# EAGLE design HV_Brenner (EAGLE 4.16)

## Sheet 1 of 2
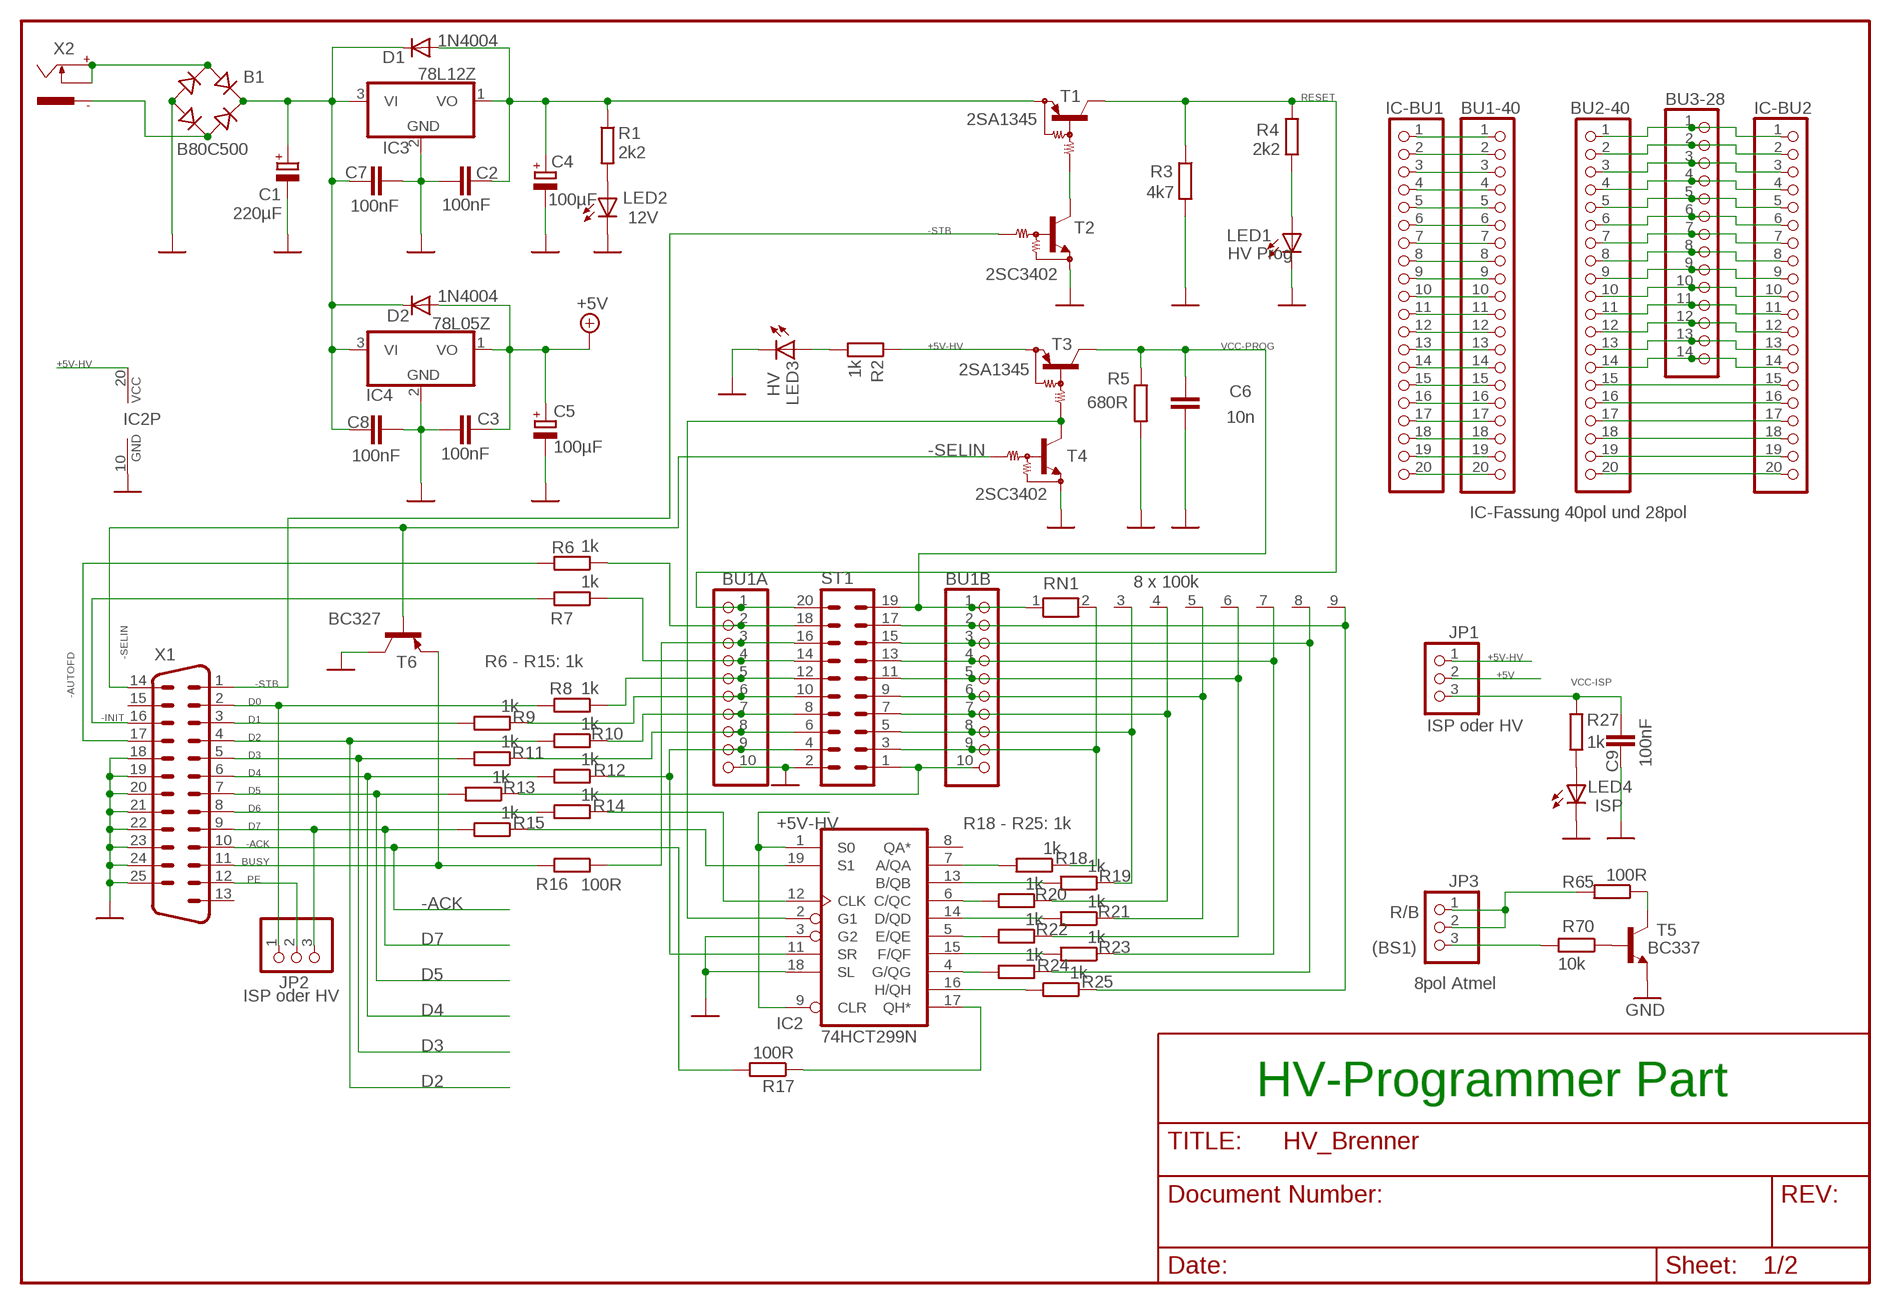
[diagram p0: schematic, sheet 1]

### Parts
B1  B80C500  B-DIL  [B-DIL]
BU1-40  PINHD-1X20  [1X20]
BU1A  PINHD-1X10  [1X10]
BU1B  PINHD-1X10  [1X10]
BU2-40  PINHD-1X20  [1X20]
BU3-28  PINHD-1X14  [1X14]
C1  220µF  CPOL-EUE3.5-8  [E3,5-8]
C2  100nF  C-EU025-024X044  [C025-024X044]
C3  100nF  C-EU025-024X044  [C025-024X044]
C4  100µF  CPOL-EUE2.5-7  [E2,5-7]
C5  100µF  CPOL-EUE2.5-7  [E2,5-7]
C6  10n  C-EU025-024X044  [C025-024X044]
C7  100nF  C-EU025-024X044  [C025-024X044]
C8  100nF  C-EU025-024X044  [C025-024X044]
C9  100nF  C-EU025-024X044  [C025-024X044]
D1  1N4004  [DO41-10]
D2  1N4004  [DO41-10]
IC2  74HCT299N  74ACT299N  [DIL20]
IC3  78L12Z  [TO92]
IC4  78L05Z  [TO92]
IC-BU1  PINHD-1X20  [1X20]
IC-BU2  PINHD-1X20  [1X20]
JP1  ISP oder HV  PINHD-1X3  [1X03]
JP2  ISP oder HV  PINHD-1X3  [1X03]
JP3  8pol Atmel  PINHD-1X3  [1X03]
LED1  HV Prog  LED3MM  [LED3MM]
LED2  12V  LED3MM  [LED3MM]
LED3  HV  LED3MM  [LED3MM]
LED4  ISP  LED3MM  [LED3MM]
R1  2k2  R-EU_0204/2V  [0204V]
R2  1k  R-EU_0204/2V  [0204V]
R3  4k7  R-EU_0204/2V  [0204V]
R4  2k2  R-EU_0204/2V  [0204V]
R5  680R  R-EU_0204/2V  [0204V]
R6  1k  R-EU_0204/2V  [0204V]
R7  1k  R-EU_0204/2V  [0204V]
R8  1k  R-EU_0204/2V  [0204V]
R9  1k  R-EU_0204/2V  [0204V]
R10  1k  R-EU_0204/2V  [0204V]
R11  1k  R-EU_0204/2V  [0204V]
R12  1k  R-EU_0204/2V  [0204V]
R13  1k  R-EU_0204/2V  [0204V]
R14  1k  R-EU_0204/2V  [0204V]
R15  1k  R-EU_0204/2V  [0204V]
R16  100R  R-EU_0204/2V  [0204V]
R17  100R  R-EU_0204/2V  [0204V]
R18  1k  R-EU_0204/2V  [0204V]
R19  1k  R-EU_0204/2V  [0204V]
R20  1k  R-EU_0204/2V  [0204V]
R21  1k  R-EU_0204/2V  [0204V]
R22  1k  R-EU_0204/2V  [0204V]
R23  1k  R-EU_0204/2V  [0204V]
R24  1k  R-EU_0204/2V  [0204V]
R25  1k  R-EU_0204/2V  [0204V]
R27  1k  R-EU_0204/2V  [0204V]
R65  100R  R-EU_0204/2V  [0204V]
R70  10k  R-EU_0204/2V  [0204V]
RN1  8 x 100k  RN08  [RN-9]
ST1  ML20  [ML20]
T1  2SA1345  2SC1345  [TO92-BCE]
T2  2SC3402  2SA3402  [TO92-BCE]
T3  2SA1345  2SC1345  [TO92-BCE]
T4  2SC3402  2SA3402  [TO92-BCE]
T5  BC337  [TO92]
T6  BC327  [TO92]
X1  M25HP  [M25HP]
X2  737992-55  [737992-5]

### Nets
#BS1: JP3.3 R70.2
#R/B: JP3.1 JP3.2 R65.2
+5V: C3.2 C5.+ D2.A IC4.1(VO) JP1.2
+5V-HV: IC2.1(S0) IC2.9(CLR) IC2.20(VCC) JP1.1 R2.1 T3.E
+12V: C2.2 C4.+ D1.A IC3.1(VO) R1.1 T1.E
+VIN: B1.+ C1.+ C7.1 C8.1 D1.C D2.C IC3.3(VI) IC4.3(VI)
-ACK: R17.2 X1.10 ; also sheet 2
-AUTOFD: R6.2 X1.17
-INIT: R7.2 X1.16
-SELIN: T4.B T6.2(B) X1.14
-STB: T2.B X1.1
AC1: B1.AC1 X2.+ X2.K
AC2: B1.AC2 X2.-1
BS1: BU1A.8 R11.1 ST1.6
BS2: BU1A.4 R7.1 ST1.14
BUSY: R16.2 T6.1(E) X1.11 ; also sheet 2
D0: JP2.1 R8.2 X1.2
D1: R9.2 X1.3 ; also sheet 2
D2: R10.2 X1.4 ; also sheet 2
D3: R11.2 X1.5 ; also sheet 2
D4: R12.2 X1.6 ; also sheet 2
D5: R13.2 X1.7 ; also sheet 2
D6: R14.2 X1.8
D7: JP2.3 R15.2 X1.9 ; also sheet 2
DATA0: BU1B.9 R18.1 RN1.2 ST1.3
DATA1: BU1B.8 R19.1 RN1.3 ST1.5
DATA2: BU1B.7 R20.1 RN1.4 ST1.7
DATA3: BU1B.6 R21.1 RN1.5 ST1.9
DATA4: BU1B.5 R22.1 RN1.6 ST1.11
DATA5: BU1B.4 R23.1 RN1.7 ST1.13
DATA6: BU1B.3 R24.1 RN1.8 ST1.15
DATA7: BU1B.2 R25.1 RN1.9 ST1.17
GND: B1.- BU1A.10 C1.- C2.1 C3.1 C4.- C5.- C6.2 C7.2 C8.2 C9.1 IC2.3(G2) IC2.10(GND) IC2.18(SL) IC3.2(GND) IC4.2(GND) LED1.K(C) LED2.K(C) LED3.K(C) LED4.K(C) R3.2 R5.2 ST1.2 T2.E T4.E T5.1(E) T6.3(C) X1.18 X1.19 X1.20 X1.21 X1.22 X1.23 X1.24 X1.25 ; also sheet 2
N$1: R65.1 T5.3(C)
N$2: LED1.A R4.2
N$4: R70.1 T5.2(B)
N$5: T1.B T2.C
N$6: IC2.2(G1) T3.B T4.C
N$34: BU2-40.1 BU3-28.1 IC-BU2.1
N$35: BU2-40.2 BU3-28.2 IC-BU2.2
N$36: BU2-40.3 BU3-28.3 IC-BU2.3
N$37: BU2-40.4 BU3-28.4 IC-BU2.4
N$38: BU2-40.5 BU3-28.5 IC-BU2.5
N$39: BU2-40.6 BU3-28.6 IC-BU2.6
N$40: BU2-40.7 BU3-28.7 IC-BU2.7
N$41: BU2-40.8 BU3-28.8 IC-BU2.8
N$42: BU2-40.9 BU3-28.9 IC-BU2.9
N$43: BU2-40.10 BU3-28.10 IC-BU2.10
N$44: BU2-40.11 BU3-28.11 IC-BU2.11
N$45: BU2-40.12 BU3-28.12 IC-BU2.12
N$46: BU2-40.13 BU3-28.13 IC-BU2.13
N$47: BU2-40.14 BU3-28.14 IC-BU2.14
N$48: BU2-40.15 IC-BU2.15
N$49: BU2-40.16 IC-BU2.16
N$50: BU2-40.17 IC-BU2.17
N$51: BU2-40.18 IC-BU2.18
N$52: BU2-40.19 IC-BU2.19
N$53: BU2-40.20 IC-BU2.20
N$54: BU1-40.1 IC-BU1.1
N$55: BU1-40.2 IC-BU1.2
N$56: BU1-40.3 IC-BU1.3
N$57: BU1-40.4 IC-BU1.4
N$58: BU1-40.5 IC-BU1.5
N$59: BU1-40.6 IC-BU1.6
N$60: BU1-40.7 IC-BU1.7
N$61: BU1-40.8 IC-BU1.8
N$62: BU1-40.9 IC-BU1.9
N$63: BU1-40.10 IC-BU1.10
N$64: BU1-40.11 IC-BU1.11
N$65: BU1-40.12 IC-BU1.12
N$66: BU1-40.13 IC-BU1.13
N$67: BU1-40.14 IC-BU1.14
N$68: BU1-40.15 IC-BU1.15
N$69: BU1-40.16 IC-BU1.16
N$70: BU1-40.17 IC-BU1.17
N$71: BU1-40.18 IC-BU1.18
N$72: BU1-40.19 IC-BU1.19
N$73: BU1-40.20 IC-BU1.20
N$74: LED2.A R1.2
N$75: IC2.17(QH*) R17.1
N$76: LED3.A R2.2
N$77: IC2.7(A/QA) R18.2
N$78: IC2.13(B/QB) R19.2
N$79: IC2.19(S1) R15.1
N$80: IC2.12(CLK) R14.1
N$81: IC2.6(C/QC) R20.2
N$82: IC2.14(D/QD) R21.2
N$83: IC2.5(E/QE) R22.2
N$84: IC2.15(F/QF) R23.2
N$85: IC2.4(G/QG) R24.2
N$86: IC2.16(H/QH) R25.2
N$166: LED4.A R27.2
OE: BU1A.6 R9.1 ST1.10
PAGEL: BU1A.2 R6.1 ST1.18
PE: JP2.2 X1.12
R/B: BU1A.3 R16.1 ST1.16
RESET: BU1A.1 R3.1 R4.1 ST1.20 T1.C
VCC-ISP: C9.2 JP1.3 R27.1 ; also sheet 2
VCC-PROG: BU1B.1 C6.1 R5.1 RN1.1 ST1.19 T3.C
WR: BU1A.7 R10.1 ST1.8
XA0: BU1A.9 IC2.11(SR) R12.1 ST1.4
XA1: BU1B.10 R13.1 ST1.1
XTAL1: BU1A.5 R8.1 ST1.12
Unconnected: IC2.8(QA*) X1.13 X1.15 X2.-2

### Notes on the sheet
- IC-Fassung 40pol und 28pol
- R6 - R15: 1k
- R18 - R25: 1k
- R/B
- (BS1)
- HV-Programmer Part

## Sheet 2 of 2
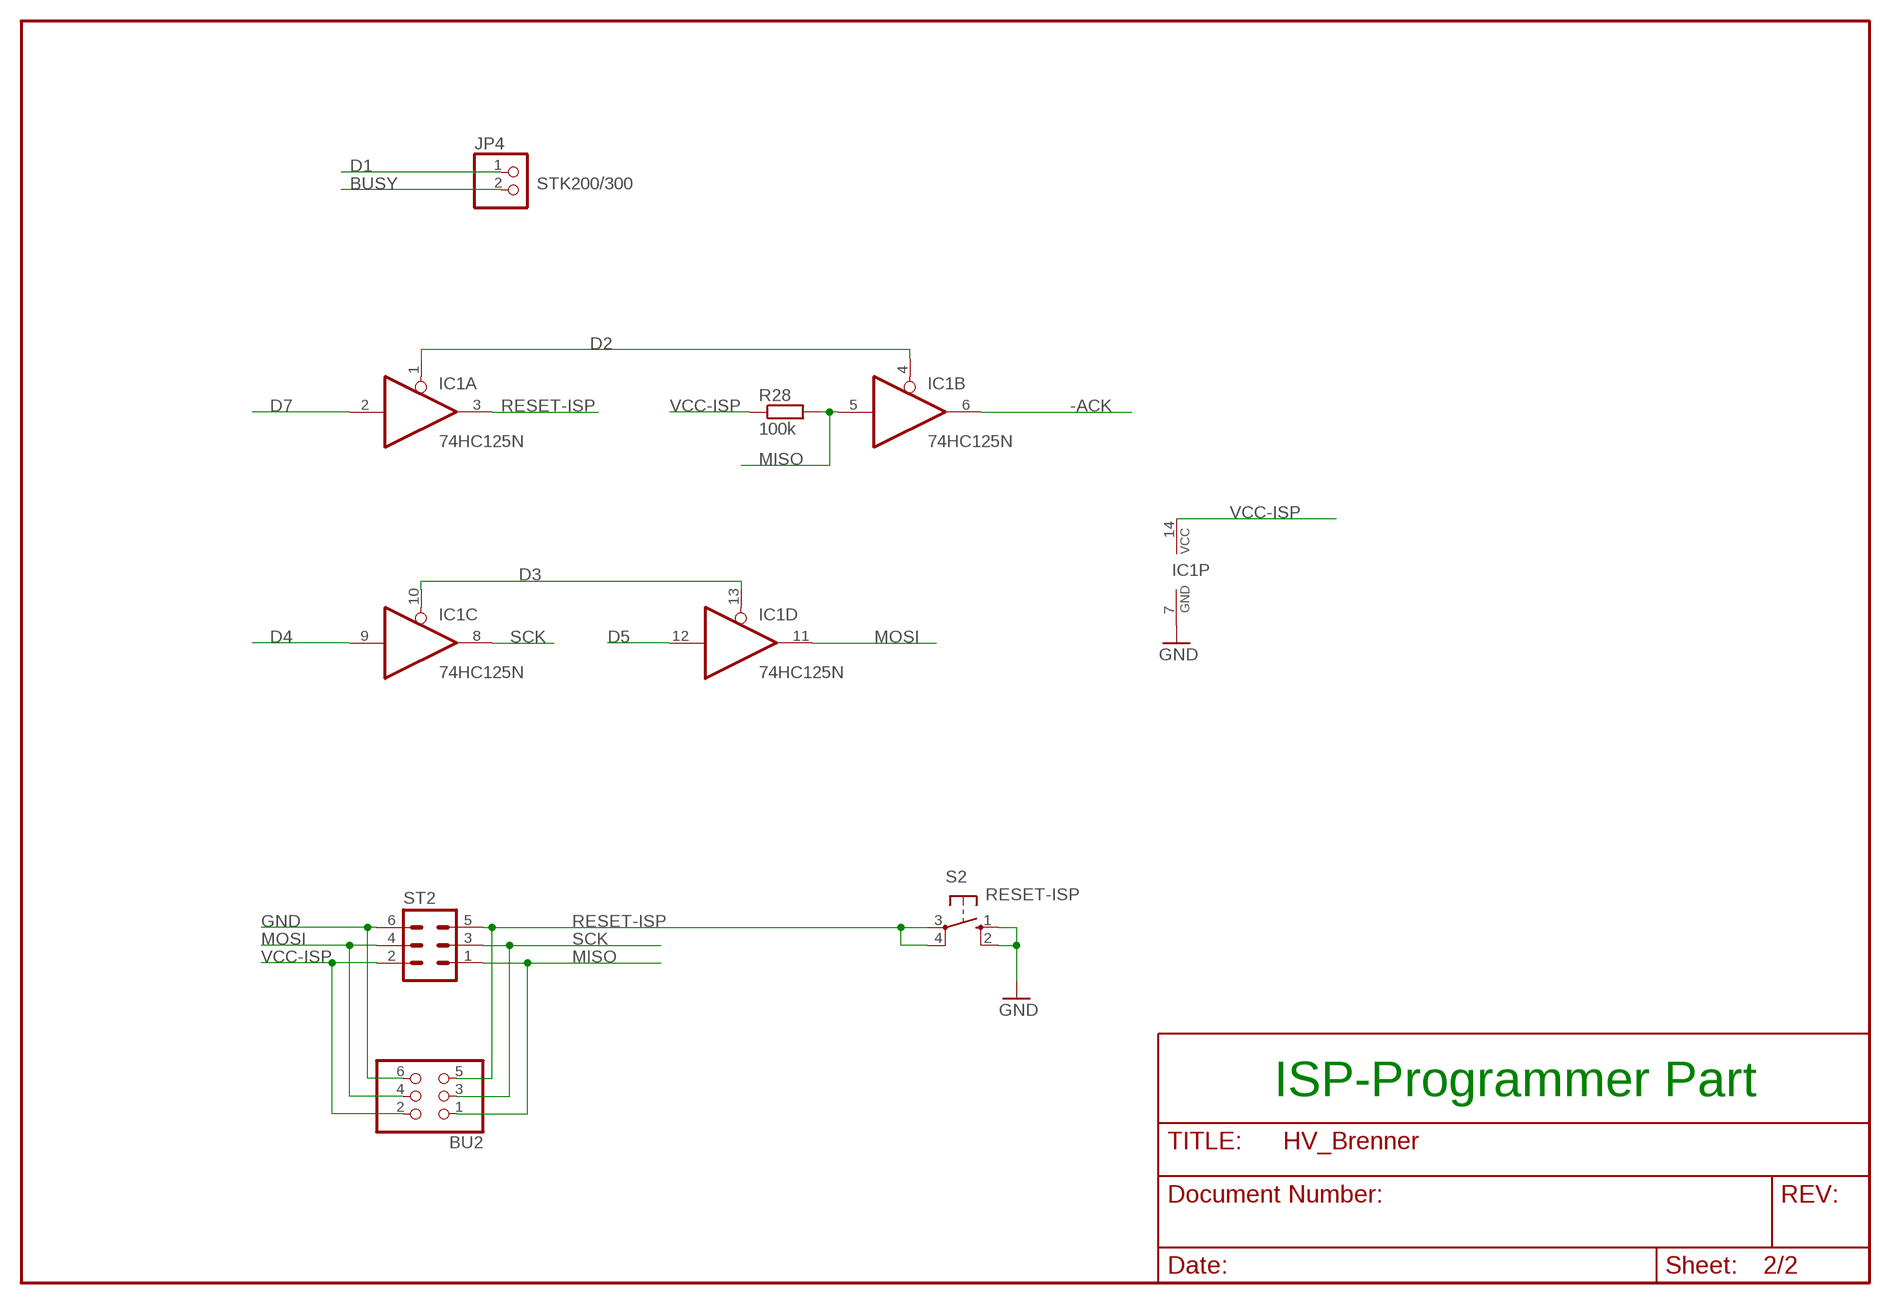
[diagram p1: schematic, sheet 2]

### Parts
BU2  PINHD-2X3  [2X03]
IC1  74HC125N  [DIL14]
JP4  PINHD-1X2  [1X02]
R28  100k  R-EU_0204/2V  [0204V]
S2  RESET-ISP  10-XX  [B3F-10XX]
ST2  ML6  [ML6]

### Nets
-ACK: IC1.6(B:O) ; also sheet 1
BUSY: JP4.2 ; also sheet 1
D1: JP4.1 ; also sheet 1
D2: IC1.1(A:OE) IC1.4(B:OE) ; also sheet 1
D3: IC1.10(C:OE) IC1.13(D:OE) ; also sheet 1
D4: IC1.9(C:I) ; also sheet 1
D5: IC1.12(D:I) ; also sheet 1
D7: IC1.2(A:I) ; also sheet 1
GND: BU2.6 IC1.7(P:GND) S2.1(S) S2.2(S1) ST2.6 ; also sheet 1
MISO: BU2.1 IC1.5(B:I) R28.2 ST2.1
MOSI: BU2.4 IC1.11(D:O) ST2.4
RESET-ISP: BU2.5 IC1.3(A:O) S2.3(P) S2.4(P1) ST2.5
SCK: BU2.3 IC1.8(C:O) ST2.3
VCC-ISP: BU2.2 IC1.14(P:VCC) R28.1 ST2.2 ; also sheet 1

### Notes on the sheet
- STK200/300
- ISP-Programmer Part

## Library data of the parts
B1 = rectifier:B-DIL: RECTIFIER
BU1-40 BU2-40 IC-BU1 IC-BU2 = pinhead:PINHD-1X20: PIN HEADER
BU1A BU1B = pinhead:PINHD-1X10: PIN HEADER
BU2 = pinhead:PINHD-2X3: PIN HEADER
BU3-28 = pinhead:PINHD-1X14: PIN HEADER
C1 C4 C5 = rcl:CPOL-EU: POLARIZED CAPACITOR, European symbol
C2 C3 C6-C9 = rcl:C-EU: CAPACITOR, European symbol
D1 D2 = diode:1N4004: DIODE
IC1 = 74xx-eu:74*125: Quad bus BUFFER, 3-state
IC2 = 74xx-eu:74*299: 8-bit universal SHIFT/STORAGE REGISTER
IC3 IC4 = linear:78*: Positive VOLTAGE REGULATOR Source: http://cache.national.com/ds/LM/LM78L05.pdf http://www.fairchildsemi.com/ds/LM/LM7805.pdf
JP1-JP3 = pinhead:PINHD-1X3: PIN HEADER
JP4 = pinhead:PINHD-1X2: PIN HEADER
LED1-LED4 = led:LED: LED
R1-R25 R27 R28 R65 R70 = rcl:R-EU_: RESISTOR, European symbol
RN1 = resistor-net:RN08: RESISTOR NETWORK
S2 = switch-omron:10-XX: OMRON SWITCH
ST1 = con-harting-ml:ML20: HARTING
ST2 = con-harting-ml:ML6: HARTING
T1 T3 = transistor:2SC1345
T2 T4 = transistor:2SA3402
T5 = transistor:BC337: NPN TRANSISTOR
T6 = transistor-pnp:BC327: PNP Transistor
X1 = con-subd:M25: SUB-D
X2 = con-conrad:737992-55: FEMALE PRINT CONNECTOR DIN 45323 (34V/3A), ROKA, distributor Conrad

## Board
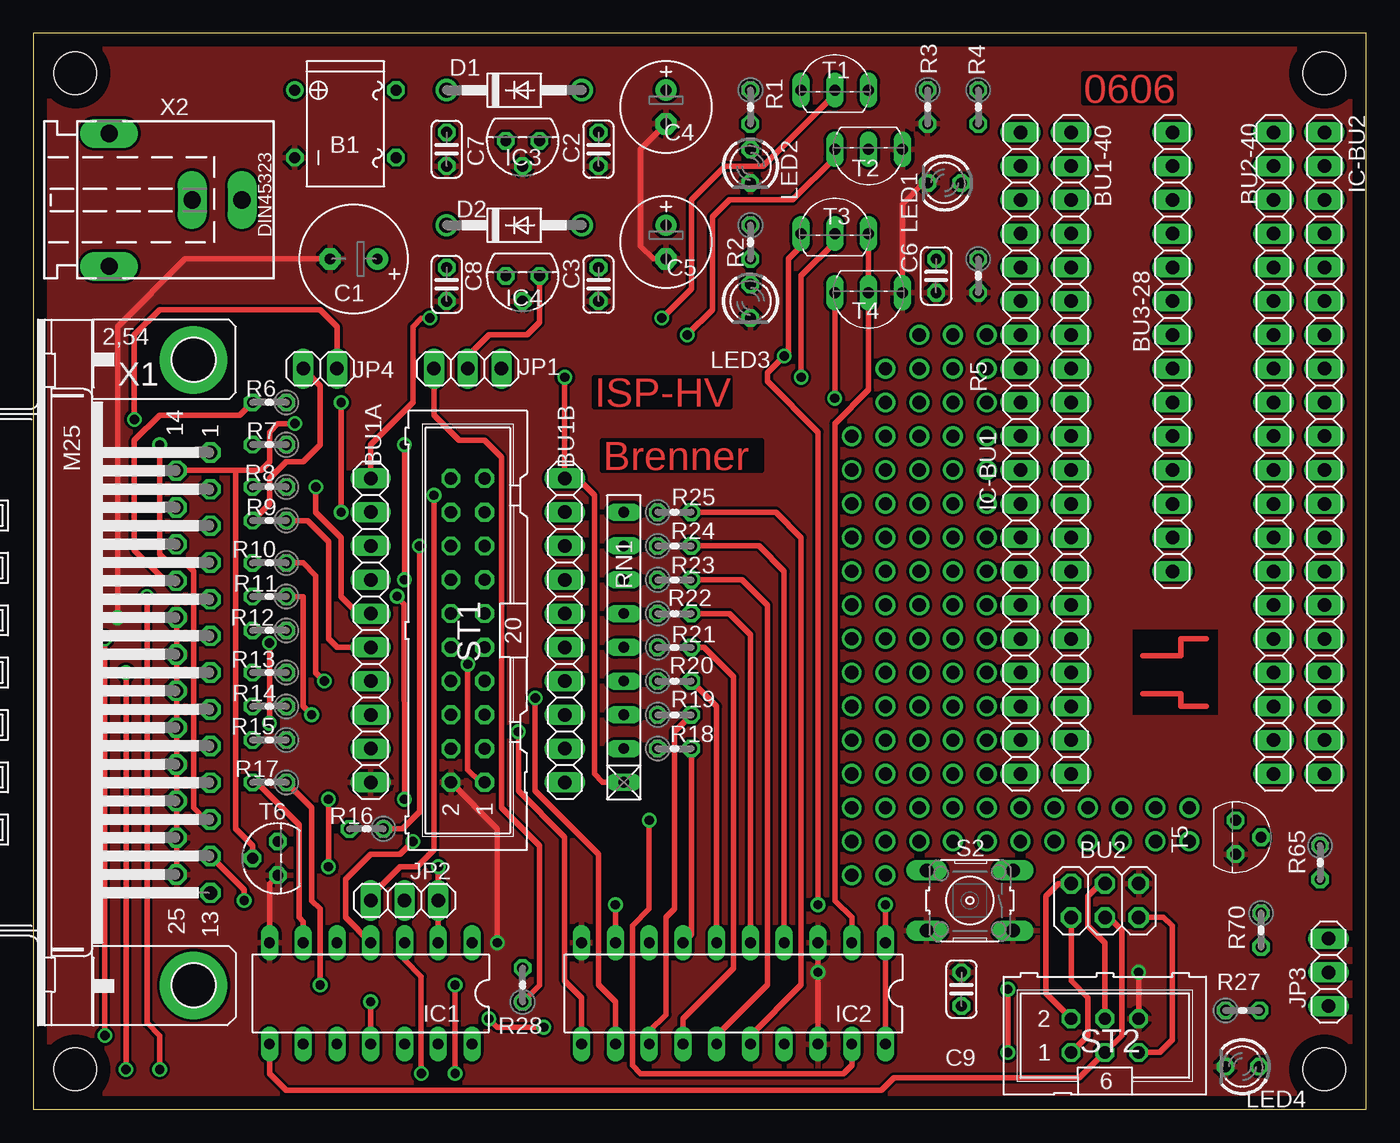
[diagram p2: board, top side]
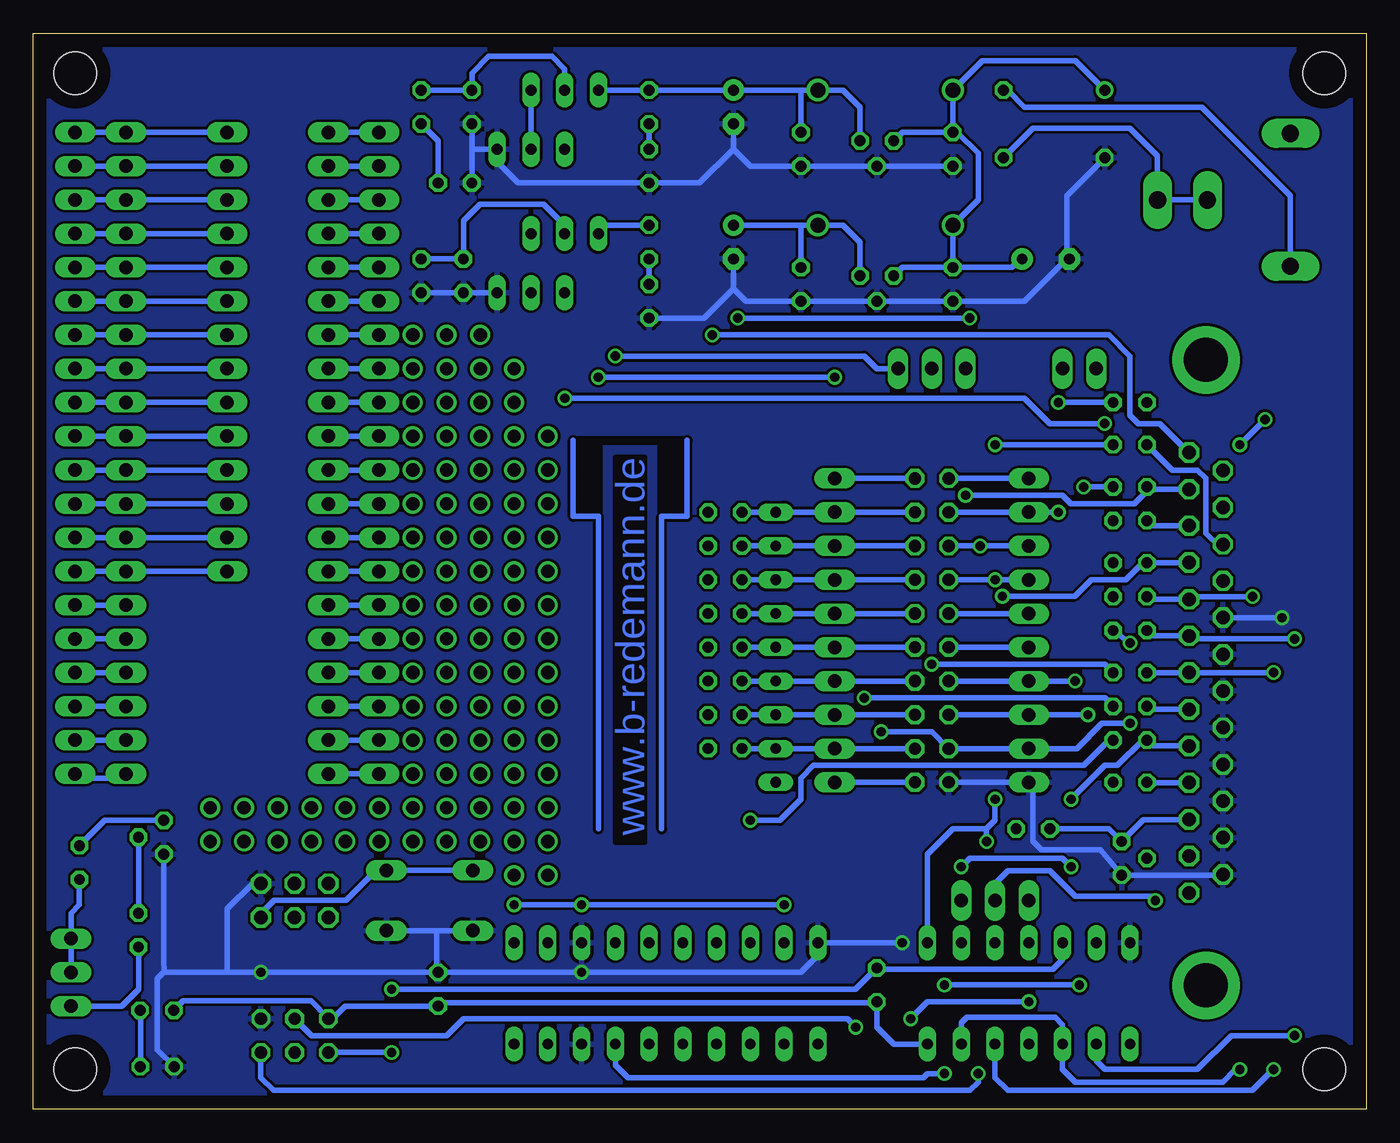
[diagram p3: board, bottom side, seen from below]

Size 100.31 x 80.95 mm. Coordinates in mm from the lower left corner, seen from the top.
Outline: 0,0 100.31,0 100.31,80.95 0,80.95 0,0
Copper layers (1+16): Top 0.035mm / dielectric 1.5mm / Bottom 0.035mm
Design rules "default": minimum track width 10mil, minimum drill 24mil, track to track 8mil, track to pad 8mil, pad to pad 8mil, via to via 8mil, smd to smd 8mil, copper to edge 40mil, drill to drill 8mil, minimum pad ring 10mil, minimum via ring 8mil, stop-mask expansion 4mil, vias tented up to drill 0mil, thermal gap 10mil
Holes 3.2 mm at 3.17,77.94 3.17,3.01 97.15,3.01 97.15,77.94
tRestrict: area 82.7,35.7 to 89.1,36.1; area 82.7,29.7 to 89.1,30.1; area 82.7,30.1 to 83.1,35.7; area 88.7,30.1 to 89.1,35.7
bRestrict: area 57.5,44.9 to 59.4,50.6; area 53.7,50 to 57.5,50.6; area 51.4,44.9 to 53.3,50.6; area 53.3,50 to 53.7,50.6

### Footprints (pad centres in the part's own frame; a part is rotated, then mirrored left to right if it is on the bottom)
B-DIL = drill 0.813 round: + -2.54,-3.81 | drill 0.813 octagon: - 2.54,-3.81; AC1 2.54,3.81; AC2 -2.54,3.81
1X20 = drill 1.016 long: 1 -24.13,0; 2 -21.59,0; 3 -19.05,0; 4 -16.51,0; 5 -13.97,0; 6 -11.43,0; 7 -8.89,0; 8 -6.35,0; 9 -3.81,0; 10 -1.27,0; 11 1.27,0; 12 3.81,0; 13 6.35,0; 14 8.89,0; 15 11.43,0; 16 13.97,0; 17 16.51,0; 18 19.05,0; 19 21.59,0; 20 24.13,0
1X10 = drill 1.016 long: 1 -11.43,0; 2 -8.89,0; 3 -6.35,0; 4 -3.81,0; 5 -1.27,0; 6 1.27,0; 7 3.81,0; 8 6.35,0; 9 8.89,0; 10 11.43,0
2X03 = drill 1.016 octagon: 1 -2.54,-1.27; 2 -2.54,1.27; 3 0,-1.27; 4 0,1.27; 5 2.54,-1.27; 6 2.54,1.27
1X14 = drill 1.016 long: 1 -16.51,0; 2 -13.97,0; 3 -11.43,0; 4 -8.89,0; 5 -6.35,0; 6 -3.81,0; 7 -1.27,0; 8 1.27,0; 9 3.81,0; 10 6.35,0; 11 8.89,0; 12 11.43,0; 13 13.97,0; 14 16.51,0
E3,5-8 = drill 0.813 pad 1.6 round: + -1.778,0 | drill 0.813 pad 1.6 octagon: - 1.778,0
C025-024X044 = drill 0.813 octagon: 1 -1.27,0; 2 1.27,0
E2,5-7 = drill 0.813 pad 1.6 round: + -1.27,0 | drill 0.813 pad 1.6 octagon: - 1.27,0
DO41-10 = drill 1.118 round: A 5.08,0; C -5.08,0
DIL14 = drill 0.813 long: 1 -7.62,-3.81; 2 -5.08,-3.81; 3 -2.54,-3.81; 4 0,-3.81; 5 2.54,-3.81; 6 5.08,-3.81; 7 7.62,-3.81; 8 7.62,3.81; 9 5.08,3.81; 10 2.54,3.81; 11 0,3.81; 12 -2.54,3.81; 13 -5.08,3.81; 14 -7.62,3.81
DIL20 = drill 0.813 long: 1 -11.43,-3.81; 2 -8.89,-3.81; 3 -6.35,-3.81; 4 -3.81,-3.81; 5 -1.27,-3.81; 6 1.27,-3.81; 7 3.81,-3.81; 8 6.35,-3.81; 9 8.89,-3.81; 10 11.43,-3.81; 11 11.43,3.81; 12 8.89,3.81; 13 6.35,3.81; 14 3.81,3.81; 15 1.27,3.81; 16 -1.27,3.81; 17 -3.81,3.81; 18 -6.35,3.81; 19 -8.89,3.81; 20 -11.43,3.81
TO92 = drill 0.813 octagon: 1 -1.27,0; 2 0,1.905; 3 1.27,0
1X03 = drill 1.016 long: 1 -2.54,0; 2 0,0; 3 2.54,0
1X02 = drill 1.016 long: 1 -1.27,0; 2 1.27,0
LED3MM = drill 0.813 octagon: A -1.27,0; K 1.27,0
0204V = drill 0.813 octagon: 1 -1.27,0; 2 1.27,0
RN-9 = drill 0.813 long: 1 -10.16,0; 2 -7.62,0; 3 -5.08,0; 4 -2.54,0; 5 0,0; 6 2.54,0; 7 5.08,0; 8 7.62,0; 9 10.16,0
B3F-10XX = drill 1.016 long: 1 -3.251,2.261; 2 3.251,2.261; 3 -3.251,-2.261; 4 3.251,-2.261
ML20 = drill 0.914 octagon: 1 -11.43,-1.27; 2 -11.43,1.27; 3 -8.89,-1.27; 4 -8.89,1.27; 5 -6.35,-1.27; 6 -6.35,1.27; 7 -3.81,-1.27; 8 -3.81,1.27; 9 -1.27,-1.27; 10 -1.27,1.27; 11 1.27,-1.27; 12 1.27,1.27; 13 3.81,-1.27; 14 3.81,1.27; 15 6.35,-1.27; 16 6.35,1.27; 17 8.89,-1.27; 18 8.89,1.27; 19 11.43,-1.27; 20 11.43,1.27
ML6 = drill 0.914 octagon: 1 -2.54,-1.27; 2 -2.54,1.27; 3 0,-1.27; 4 0,1.27; 5 2.54,-1.27; 6 2.54,1.27
TO92-BCE = drill 0.813 long: B 2.54,0; C 0,0; E -2.54,0
TO92' = drill 0.813 octagon: 1 1.27,0; 2 0,1.905; 3 -1.27,0
M25HP = drill 1.016 octagon: 1 -16.561,1.27; 2 -13.792,1.27; 3 -11.049,1.27; 4 -8.28,1.27; 5 -5.512,1.27; 6 -2.769,1.27; 7 0,1.27; 8 2.769,1.27; 9 5.512,1.27; 10 8.28,1.27; 11 11.049,1.27; 12 13.792,1.27; 13 16.561,1.27; 14 -15.189,-1.27; 15 -12.421,-1.27; 16 -9.652,-1.27; 17 -6.909,-1.27; 18 -4.14,-1.27; 19 -1.372,-1.27; 20 1.372,-1.27; 21 4.14,-1.27; 22 6.909,-1.27; 23 9.652,-1.27; 24 12.421,-1.27; 25 15.189,-1.27 | drill 3.302 pad 5.08 round: G1 -23.52,0; G2 23.52,0
737992-5 = drill 1.3 pad 2.184 long: + 0,10; -1 5,0; -2 -5,0; K 0,6.25

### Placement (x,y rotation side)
B1  23.49,74.13 270 top
BU1-40  78.1,49.37 270 top
BU1A  25.39,36.03 270 top
BU1B  40,36.03 270 top
BU2  80.64,15.71 0 top
BU2-40  93.34,49.37 270 top
BU3-28  85.72,56.98 270 top
C1  24.12,63.97 180 top
C2  42.54,72.22 90 top
C3  42.54,62.06 90 top
C4  47.62,75.4 270 top
C5  47.62,65.24 270 top
C6  67.94,62.7 270 top
C7  31.11,72.22 270 top
C8  31.11,62.06 270 top
C9  69.84,9.04 270 top
D1  36.19,76.67 0 top
D2  36.19,66.51 0 top
IC1  25.39,8.73 180 top
IC2  52.7,8.73 180 top
IC3  36.83,72.86 180 top
IC4  36.83,62.7 180 top
IC-BU1  74.29,49.37 270 top
IC-BU2  97.15,49.37 270 top
JP1  32.7,55.71 180 top
JP2  27.93,15.71 0 top
JP3  97.47,10.31 270 top
JP4  21.58,55.71 0 top
LED1  68.57,69.69 180 top
LED2  53.97,70.95 270 top
LED3  53.97,60.8 270 top
LED4  90.98,3.21 180 top
R1  53.97,75.4 270 top
R2  53.97,65.24 270 top
R3  67.3,75.4 270 top
R4  71.11,75.4 270 top
R5  71.11,62.7 270 top
R6  17.77,53.17 180 top
R7  17.77,50 180 top
R8  17.77,46.82 180 top
R9  17.77,44.28 180 top
R10  17.77,41.11 180 top
R11  17.77,38.57 180 top
R12  17.77,36.03 180 top
R13  17.77,32.85 180 top
R14  17.77,30.31 180 top
R15  17.77,27.77 180 top
R16  25.08,21.11 180 top
R17  17.77,24.6 180 top
R18  48.26,27.14 0 top
R19  48.26,29.68 0 top
R20  48.26,32.22 0 top
R21  48.26,34.76 0 top
R22  48.26,37.3 0 top
R23  48.26,39.84 0 top
R24  48.26,42.38 0 top
R25  48.26,44.92 0 top
R27  91,7.45 0 top
R28  36.83,9.36 90 top
R65  96.83,18.57 270 top
R70  92.39,13.49 270 top
RN1  44.45,34.76 90 top
S2  70.48,15.71 180 top
ST1  32.7,36.03 90 top
ST2  80.64,5.55 0 top
T1  60.32,76.67 0 top
T2  62.86,72.22 180 top
T3  60.32,65.88 0 top
T4  62.86,61.43 180 top
T5  BC337  [TO92']  90.48,20.47 270 top
T6  BC327  [TO92']  18.41,18.88 90 top
X1  12.06,32.85 270 top
X2  5.71,68.41 270 top

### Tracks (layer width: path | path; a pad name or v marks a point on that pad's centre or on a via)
#BS1
  Bottom 0.406: R70.2 92.39,9.04 93.66,7.77 JP3.3
#R/B
  Bottom 0.406: R65.2 96.83,15.39 97.47,14.76 JP3.1 | JP3.1 97.47,12.54 | JP3.2 JP3.1
+5V
  Top 0.406: JP1.2 32.7,56.67 34.29,58.25 37.14,58.25 38.1,59.21 IC4.1
  Bottom 0.406: IC4.1 38.1,65.24 39.37,66.51 D2.A 42.54,66.51 | 42.54,66.51 C5.+ | 42.54,66.51 C3.2
+5V-HV  (via drill 0.7)
  Top 0.406: IC2.9 v43.81,15.39 | v64.13,15.39 IC2.1 IC2.20 | T3.E 57.78,64.92 56.83,63.97 56.83,56.98 v56.51,56.67 55.24,55.4 55.24,54.76 59.05,50.95 v59.05,15.39
  Bottom 0.406: v43.81,15.39 v59.05,15.39 v64.13,15.39 | JP1.1 36.83,55.71 37.78,56.67 v56.51,56.67 | T3.E 57.73,65.88 57.73,66.51 R2.1
+12V
  Bottom 0.406: IC3.1 38.1,75.4 39.37,76.67 D1.A 42.54,76.67 | 42.54,76.67 C4.+ R1.1 T1.E | 42.54,76.67 C2.2
+VIN
  Bottom 0.406: B1.+ 21.9,78.89 28.89,78.89 D1.C C7.1 | C7.1 34.92,73.5 IC3.3 | C7.1 30.79,73.5 29.2,71.91 29.2,68.41 D2.C C8.1 | C1.+ 26.03,63.97 26.66,63.34 C8.1 | C8.1 34.92,63.34 IC4.3
-ACK
  Top 0.406: IC1.6 20.31,14.12 20,14.44 20,21.42 16.85,24.57 16.85,24.6 R17.2
  Bottom 0.406: X1.10 16.48,24.57 R17.2
-AUTOFD
  Top 0.406: R6.2 15.55,52.22 9.52,52.22 7.62,50.32 7.62,42.06 9.84,39.84 11.11,39.84 10.79,39.52 X1.17
-INIT
  Bottom 0.406: R7.2 14.6,48.09 12.7,48.09 12.06,47.46 12.06,43.33 11.11,42.38 10.98,42.51 X1.16
-SELIN  (via drill 0.7)
  Top 0.406: T6.2 16.5,19.84 15.24,21.11 15.24,36.66 | 15.24,36.66 15.24,37.94 | 15.24,36.66 15.24,48.09 | X1.14 10.79,48.09 15.24,48.09 | 15.24,48.09 17.14,48.09 17.77,48.73 17.77,50.95 18.41,51.59 v19.68,51.59 | v60.32,53.49 T4.B v60.32,53.49
  Bottom 0.406: v19.68,51.59 23.81,51.59 25.71,53.49 v60.32,53.49
-STB  (via drill 0.7)
  Top 0.406: T2.B 60.32,71.59 57.15,68.41 52.38,68.41 51.11,67.14 51.11,60.16 v49.21,58.25
  Bottom 0.406: v49.21,58.25 19.36,58.25 17.77,56.67 17.77,52.22 17.14,51.59 15.55,51.59 13.33,49.37 X1.1
AC1
  Bottom 0.406: X2.K X2.+ 15.71,71.75 17.77,73.81 25.08,73.81 B1.AC1
AC2
  Bottom 0.406: X2.-1 5.71,68.73 12.38,75.4 25.71,75.4 26.98,76.67 B1.AC2
BS1  (via drill 0.7)
  Top 0.406: R11.1 20.31,38.57 20.31,30.31 v20.95,29.68
  Bottom 0.406: ST1.6 BU1A.8 v20.95,29.68
BS2  (via drill 0.7)
  Top 0.406: v27.93,39.84 v27.93,50
  Bottom 0.406: BU1A.4 ST1.14 | BU1A.4 24.76,39.84 | BU1A.4 v27.93,39.84 | v27.93,50 R7.1
BUSY  (via drill 0.7)
  Top 0.406: JP4.2 22.86,58.89 21.58,60.16 9.52,60.16 7.62,58.25 v7.62,51.91 | X1.11 12.95,21.81 12.06,22.7 12.06,40.48 11.43,41.11 10.16,41.11 9.52,41.74 v9.52,50
  Bottom 0.406: X1.11 16.76,21.81 T6.1 19.36,21.11 R16.2 | v9.52,50 v7.62,51.91
D0  (via drill 0.7)
  Top 0.406: JP2.1 25.39,16.03 27.62,18.25 28.89,18.25 30.16,19.52 v30.16,46.19
  Bottom 0.406: 16.33,46.65 X1.2 | 16.33,46.65 R8.2 | 16.33,46.65 16.36,46.65 17.46,45.55 22.22,45.55 22.86,46.19 v30.16,46.19
D1
  Top 0.406: JP4.1 21.58,54.45 21.58,50 20.31,48.73 19.04,48.73 17.77,47.46 17.77,45.55 R9.2
  Bottom 0.406: X1.3 16.12,43.9 R9.2
D2  (via drill 0.7)
  Top 0.406: v27.93,23.33 27.91,38.01 27.38,38.54 v27.38,38.6 | IC1.4 23.49,14.44 23.49,17.3 25.39,19.2 27.62,19.2 v28.57,20.15
  Bottom 0.406: X1.4 16.48,41.13 R10.2 16.82,41.11 18.09,39.84 20.69,39.84 21.94,38.6 v27.38,38.6 | v27.93,23.33 27.93,21.74 28.57,21.11 | 28.57,21.11 31.11,21.11 33.02,19.2 IC1.1 | v28.57,20.15 28.57,21.11
D3  (via drill 0.7)
  Top 0.406: v9.52,3.01 9.52,5.55 8.57,6.5 v8.57,38.57
  Bottom 0.406: R11.2 16.3,38.37 X1.5 13.33,38.57 v8.57,38.57 | v9.52,3.01 9.84,3.01 10.79,2.06 21.9,2.06 22.86,3.01 IC1.10 22.86,6.38 23.39,6.92 30.06,6.92 30.47,6.5 IC1.13 30.47,6.04
D4  (via drill 0.7)
  Top 0.406: v5.39,5.55 v5.39,35.39
  Bottom 0.406: R12.2 16.1,35.62 X1.6 13.33,35.39 v5.39,35.39 | IC1.9 20.31,3.64 19.68,3.01 12.7,3.01 10.16,5.55 v5.39,5.55
D5  (via drill 0.7)
  Top 0.406: v6.98,3.01 v6.98,32.85
  Bottom 0.406: R13.2 X1.7 v6.98,32.85 | IC1.12 27.93,2.38 26.98,1.42 8.57,1.42 v6.98,3.01
D6
  Bottom 0.406: X1.8 16.28,30.09 R14.2
D7  (via drill 0.7)
  Top 0.406: v22.22,18.25 v22.22,23.33 | v30.47,18.25 JP2.3 IC1.2
  Bottom 0.406: X1.9 16.07,27.34 R15.2 16.82,27.77 18.73,25.87 19.68,25.87 v22.22,23.33 | v30.47,18.25 29.84,18.88 22.86,18.88 v22.22,18.25
DATA0
  Bottom 0.406: ST1.3 BU1B.9 RN1.2 R18.1
DATA1
  Bottom 0.406: ST1.5 BU1B.8 RN1.3 R19.1
DATA2
  Bottom 0.406: ST1.7 BU1B.7 RN1.4 R20.1
DATA3
  Bottom 0.406: ST1.9 BU1B.6 RN1.5 R21.1
DATA4
  Bottom 0.406: ST1.11 BU1B.5 RN1.6 R22.1
DATA5
  Bottom 0.406: ST1.13 BU1B.4 RN1.7 R23.1
DATA6
  Bottom 0.406: ST1.15 BU1B.3 RN1.8 R24.1
DATA7
  Bottom 0.406: ST1.17 BU1B.2 RN1.9 R25.1
GND  (via drill 0.7)
  Top 0.406: X1.19 10.79,34.12 | X1.19 X1.18 | X1.19 X1.20 X1.21 X1.22 | X1.22 10.79,25.87 | X1.22 X1.23 X1.24 | X1.24 10.79,20.15 | 10.79,17.61 X1.25 X1.24 | T6.3 17.77,16.98 IC1.7 | ST1.2 34.92,21.11 v34.92,12.54 | v59.05,10.31 IC2.18 | v59.05,10.31 IC2.3 | v59.05,10.31 IC2.3 | v83.18,10.31 ST2.6 | v59.05,10.31 IC2.3 | C5.- 46.67,63.97 45.72,64.92 45.72,72.22 C4.- | T4.E 65.4,68.1 66.99,69.69 LED1.K | v6.34,36.98 6.34,58.89 11.43,63.97 C1.-
  Bottom 0.406: ST1.2 BU1A.10 25.08,24.6 25.08,20.15 | X1.25 10.84,17.61 T6.3 20,19.52 24.44,19.52 25.08,20.15 | v34.92,12.54 IC2.10 41.27,11.58 42.54,10.31 v59.05,10.31 C9.1 | 85.72,10.31 v83.18,10.31 C9.1 | 85.72,10.31 90.48,10.31 | B1.- 22.54,68.73 22.54,64.29 22.22,63.97 C1.- 22.54,63.97 25.71,60.8 C8.2 IC4.2 C3.1 46.67,60.8 47.62,61.75 | C7.2 IC3.2 C2.1 46.35,70.95 47.62,72.22 | C4.- 47.62,72.22 | 47.62,72.22 50.16,69.69 LED2.K 63.81,69.69 65.4,71.27 T2.E 67.3,72.22 | 47.62,61.75 C5.- | LED3.K 49.84,59.52 47.62,61.75 | R5.2 C6.2 T4.E | 67.3,72.22 R3.2 | X1.18 6.36,36.99 v6.34,36.98 | 25.08,20.15 25.09,20.17 | 67.3,72.22 LED1.K | T5.1 90.48,11.27 90.47,10.31 90.48,10.31 | 90.48,10.31 90.96,9.83 90.96,4.5 89.68,3.21 LED4.K | 73.69,13.45 S2.1 | 69.97,13.45 S2.2 | 69.97,13.45 73.69,13.45 | 73.69,13.45 | C9.1 69.97,10.31 69.97,13.45 | BU2.6 83.81,16.98 85.72,15.08 85.72,10.31
  pour Bottom: 99.69,80.48 99.69,0.47 0.63,0.47 -0.01,80.48
  pour Top: 99.69,80.48 99.69,0.47 0.63,0.47 -0.01,79.84 0.63,80.48
MISO  (via drill 0.7)
  Top 0.406: v73.34,9.04 v73.34,4.28 | ST2.1 79.37,5.55 79.37,8.41 78.1,9.68 BU2.1 | BU2.1 78.1,14.46 | BU2.1
  Bottom 0.406: IC1.5 22.86,11.27 23.59,10.53 35.14,10.53 36.82,10.53 36.81,10.53 36.81,10.63 | v73.34,4.28 ST2.1 | 36.81,10.63 36.81,10.67 | 36.81,10.63 R28.2 38.43,9.04 v73.34,9.04
MOSI  (via drill 0.7)
  Top 0.406: v34.29,6.82 34.92,6.18 v38.41,6.18 | IC1.11 v25.39,8.09 | ST2.4 80.64,12.54 79.37,13.81 79.37,16.03 80.28,16.94 80.6,16.94 BU2.4
  Bottom 0.406: ST2.4 79.37,5.55 69.21,5.55 67.94,6.82 39.05,6.82 v38.41,6.18 | v34.29,6.82 33.02,8.09 v25.39,8.09
N$1
  Bottom 0.406: T5.3 94.93,21.74 R65.1
N$2
  Bottom 0.406: R4.2 69.84,72.86 LED1.A
N$4
  Bottom 0.406: 92.39,14.44 R70.1 T5.2
N$5
  Bottom 0.406: T2.C T1.B
N$6
  Top 0.406: T3.B T4.C 62.86,54.13 60.32,51.59 60.32,15.71 61.59,14.44 IC2.2
N$7  (via drill 1)
  other vias: 61.59,22.7
N$8  (via drill 1)
  other vias: 64.13,22.7
N$9  (via drill 1)
  other vias: 66.67,40.48
N$10  (via drill 1)
  other vias: 69.21,40.48
N$11  (via drill 1)
  other vias: 64.13,43.02
N$12  (via drill 1)
  other vias: 71.75,40.48
N$13  (via drill 1)
  other vias: 69.21,37.94
N$14  (via drill 1)
  other vias: 66.67,37.94
N$15  (via drill 1)
  other vias: 64.13,37.94
N$16  (via drill 1)
  other vias: 61.59,37.94
N$17  (via drill 1)
  other vias: 61.59,40.48
N$18  (via drill 1)
  other vias: 64.13,40.48
N$19  (via drill 1)
  other vias: 61.59,35.39
N$20  (via drill 1)
  other vias: 64.13,35.39
N$21  (via drill 1)
  other vias: 66.67,32.85
N$22  (via drill 1)
  other vias: 66.67,35.39
N$23  (via drill 1)
  other vias: 69.21,25.23
N$24  (via drill 1)
  other vias: 71.75,37.94
N$25  (via drill 1)
  other vias: 69.21,35.39
N$26  (via drill 1)
  other vias: 61.59,32.85
N$27  (via drill 1)
  other vias: 61.59,30.31
N$28  (via drill 1)
  other vias: 64.13,32.85
N$29  (via drill 1)
  other vias: 64.13,30.31
N$30  (via drill 1)
  other vias: 66.67,30.31
N$31  (via drill 1)
  other vias: 69.21,32.85
N$32  (via drill 1)
  other vias: 71.75,32.85
N$33  (via drill 1)
  other vias: 71.75,35.39
N$34
  Bottom 0.406: 93.66,73.5 IC-BU2.1 | 93.66,73.5 BU2-40.1 | BU3-28.1 93.66,73.5
N$35
  Bottom 0.406: 97.47,70.95 IC-BU2.2 BU2-40.2 BU3-28.2
N$36
  Bottom 0.406: IC-BU2.3 BU2-40.3 BU3-28.3
N$37
  Bottom 0.406: IC-BU2.4 BU2-40.4 93.02,65.88 | BU3-28.4 93.02,65.88 | 93.02,65.88 93.02,65.56
N$38
  Bottom 0.406: BU2-40.5 IC-BU2.5 | BU3-28.5 BU2-40.5 | BU2-40.5 93.34,63.02
N$39
  Bottom 0.406: IC-BU2.6 BU2-40.6 BU3-28.6
N$40
  Bottom 0.406: 93.66,58.25 IC-BU2.7 | 93.66,58.25 BU2-40.7 | BU3-28.7 93.66,58.25
N$41
  Bottom 0.406: BU2-40.8 IC-BU2.8 | BU3-28.8 BU2-40.8 | BU2-40.8 93.34,56.03
N$42
  Bottom 0.406: 97.47,53.17 IC-BU2.9 BU2-40.9 BU3-28.9
N$43
  Bottom 0.406: 97.47,50.63 IC-BU2.10 BU2-40.10 | BU3-28.10 BU2-40.10 | BU2-40.10 93.34,50.95
N$44
  Bottom 0.406: IC-BU2.11 BU2-40.11 93.66,48.09 | BU3-28.11 93.66,48.09 | 93.66,48.09 93.66,47.78
N$45
  Bottom 0.406: 93.66,45.55 IC-BU2.12 | 93.66,45.55 BU2-40.12 | BU3-28.12 93.66,45.55
N$46
  Bottom 0.406: 93.66,43.02 IC-BU2.13 | 93.66,43.02 BU2-40.13 | BU3-28.13 93.66,43.02
N$47
  Bottom 0.406: IC-BU2.14 BU2-40.14 BU3-28.14
N$48
  Bottom 0.406: BU2-40.15 IC-BU2.15
N$49
  Bottom 0.406: BU2-40.16 IC-BU2.16
N$50
  Bottom 0.406: BU2-40.17 IC-BU2.17
N$51
  Bottom 0.406: 97.47,30.31 IC-BU2.18 BU2-40.18
N$52
  Bottom 0.406: BU2-40.19 IC-BU2.19
N$53
  Bottom 0.406: IC-BU2.20 97.15,24.92 93.66,24.92 BU2-40.20
N$54
  Bottom 0.406: IC-BU1.1 BU1-40.1
N$55
  Bottom 0.406: IC-BU1.2 BU1-40.2
N$56
  Bottom 0.406: IC-BU1.3 BU1-40.3
N$57
  Bottom 0.406: IC-BU1.4 BU1-40.4
N$58
  Bottom 0.406: IC-BU1.5 BU1-40.5
N$59
  Bottom 0.406: IC-BU1.6 BU1-40.6
N$60
  Bottom 0.406: IC-BU1.7 BU1-40.7
N$61
  Bottom 0.406: 78.42,55.71 BU1-40.8 IC-BU1.8
N$62
  Bottom 0.406: IC-BU1.9 BU1-40.9
N$63
  Bottom 0.406: IC-BU1.10 BU1-40.10
N$64
  Bottom 0.406: IC-BU1.11 BU1-40.11
N$65
  Bottom 0.406: IC-BU1.12 BU1-40.12
N$66
  Bottom 0.406: IC-BU1.13 BU1-40.13 78.42,42.7
N$67
  Bottom 0.406: IC-BU1.14 BU1-40.14
N$68
  Bottom 0.406: IC-BU1.15 BU1-40.15
N$69
  Bottom 0.406: IC-BU1.16 BU1-40.16
N$70
  Bottom 0.406: IC-BU1.17 BU1-40.17
N$71
  Bottom 0.406: IC-BU1.18 BU1-40.18
N$72
  Bottom 0.406: IC-BU1.19 BU1-40.19
N$73
  Bottom 0.406: IC-BU1.20 BU1-40.20
N$74
  Bottom 0.406: LED2.A R1.2
N$75  (via drill 0.7)
  Top 0.406: R17.1 20.95,22.7 20.95,15.71 21.58,15.08 v21.58,9.36 | v31.74,9.36 v31.74,2.69
  Bottom 0.406: IC2.17 56.51,3.33 55.56,2.38 33.33,2.38 33.02,2.69 v31.74,2.69 | v21.58,9.36 v31.74,9.36
N$76
  Bottom 0.406: LED3.A 53.65,62.06 53.97,62.38 R2.2
N$77
  Top 0.406: R18.2 49.53,13.17 IC2.7
N$78
  Top 0.406: R19.2 48.26,28.41 48.26,15.08 47.62,14.44 47.62,7.14 46.35,5.87 IC2.13
N$79  (via drill 0.7)
  Top 0.406: v46.35,21.74 46.35,15.08 45.08,13.81 45.08,3.33 45.72,2.69 60.96,2.69 61.59,3.33 IC2.19
  Bottom 0.406: R15.1 19.36,27.77 21.27,25.87 41.59,25.87 42.54,24.92 42.54,23.33 44.13,21.74 v46.35,21.74
N$80  (via drill 0.7)
  Top 0.406: v37.78,30.95 37.78,23.96 42.54,19.2 42.54,9.36 43.81,8.09 IC2.12
  Bottom 0.406: R14.1 19.68,30.95 v37.78,30.95
N$81
  Top 0.406: R20.2 51.43,30.31 IC2.6
N$82
  Top 0.406: R21.2 50.48,34.76 52.7,32.54 52.7,10.63 48.89,6.82 IC2.14
N$83
  Top 0.406: IC2.5 53.97,35.71 52.38,37.3 R22.2
N$84
  Top 0.406: IC2.15 51.43,5.55 55.24,9.36 55.24,37.94 53.34,39.84 R23.2
N$85
  Top 0.406: IC2.4 56.51,40.48 54.61,42.38 49.84,42.38 49.53,42.7 R24.2
N$86
  Top 0.406: IC2.16 53.97,5.55 57.78,9.36 57.78,43.02 55.88,44.92 49.84,44.92 49.53,45.24 R25.2
N$87  (via drill 1)
  other vias: 71.75,30.31
N$88  (via drill 1)
  other vias: 69.21,30.31
N$89  (via drill 1)
  other vias: 66.67,25.23
N$90  (via drill 1)
  other vias: 69.21,27.77
N$91  (via drill 1)
  other vias: 71.75,27.77
N$92  (via drill 1)
  other vias: 66.67,27.77
N$93  (via drill 1)
  other vias: 64.13,27.77
N$94  (via drill 1)
  other vias: 61.59,27.77
N$95  (via drill 1)
  other vias: 66.67,55.71
N$96  (via drill 1)
  other vias: 69.21,58.25
N$97  (via drill 1)
  other vias: 71.75,58.25
N$98  (via drill 1)
  other vias: 69.21,55.71
N$99  (via drill 1)
  other vias: 66.67,58.25
N$100  (via drill 1)
  other vias: 64.13,55.71
N$101  (via drill 1)
  other vias: 64.13,53.17
N$102  (via drill 1)
  other vias: 66.67,53.17
N$103  (via drill 1)
  other vias: 69.21,53.17
N$104  (via drill 1)
  other vias: 71.75,55.71
N$105  (via drill 1)
  other vias: 71.75,53.17
N$106  (via drill 1)
  other vias: 64.13,50.63
N$107  (via drill 1)
  other vias: 71.75,45.55
N$108  (via drill 1)
  other vias: 71.75,43.02
N$109  (via drill 1)
  other vias: 69.21,43.02
N$110  (via drill 1)
  other vias: 69.21,45.55
N$111  (via drill 1)
  other vias: 71.75,48.09
N$112  (via drill 1)
  other vias: 71.75,50.63
N$113  (via drill 1)
  other vias: 69.21,50.63
N$114  (via drill 1)
  other vias: 69.21,48.09
N$115  (via drill 1)
  other vias: 66.67,50.63
N$116  (via drill 1)
  other vias: 64.13,48.09
N$117  (via drill 1)
  other vias: 61.59,50.63
N$118  (via drill 1)
  other vias: 61.59,48.09
N$119  (via drill 1)
  other vias: 61.59,45.55
N$120  (via drill 1)
  other vias: 66.67,48.09
N$121  (via drill 1)
  other vias: 64.13,45.55
N$122  (via drill 1)
  other vias: 66.67,45.55
N$123  (via drill 1)
  other vias: 66.67,43.02
N$124  (via drill 1)
  other vias: 61.59,43.02
N$125  (via drill 1)
  other vias: 86.99,20.15
N$126  (via drill 1)
  other vias: 84.45,20.15
N$127  (via drill 1)
  other vias: 81.91,20.15
N$128  (via drill 1)
  other vias: 79.37,20.15
N$129  (via drill 1)
  other vias: 76.83,20.15
N$130  (via drill 1)
  other vias: 86.99,22.7
N$131  (via drill 1)
  other vias: 71.75,20.15
N$132  (via drill 1)
  other vias: 71.75,25.23
N$133  (via drill 1)
  other vias: 69.21,22.7
N$134  (via drill 1)
  other vias: 66.67,22.7
N$135  (via drill 1)
  other vias: 64.13,25.23
N$136  (via drill 1)
  other vias: 61.59,25.23
N$137  (via drill 1)
  other vias: 61.59,20.15
N$138  (via drill 1)
  other vias: 64.13,20.15
N$139  (via drill 1)
  other vias: 66.67,20.15
N$140  (via drill 1)
  other vias: 69.21,20.15
N$141  (via drill 1)
  other vias: 61.59,17.61
N$142  (via drill 1)
  other vias: 64.13,17.61
N$146  (via drill 1)
  other vias: 74.29,20.15
N$155  (via drill 1)
  other vias: 71.75,22.7
N$156  (via drill 1)
  other vias: 74.29,22.7
N$157  (via drill 1)
  other vias: 76.83,22.7
N$158  (via drill 1)
  other vias: 79.37,22.7
N$159  (via drill 1)
  other vias: 81.91,22.7
N$160  (via drill 1)
  other vias: 84.45,22.7
N$161
  Bottom 0.406: 53.02,21.11 53.02,44.6 51.11,44.6 51.11,50.32
N$162
  Bottom 0.406: 57.78,21.11 57.78,44.6 59.69,44.6 59.69,50.32
N$163
  Top 0.406: 88.26,35.39 86.35,35.39 86.35,34.12 83.5,34.12
N$164
  Top 0.406: 83.5,31.27 86.35,31.27 86.35,30.31 88.26,30.31
N$166
  Bottom 0.406: 92.23,7.45 92.23,7.59 | 92.23,7.45 R27.2 | LED4.A 92.23,3.21 92.23,7.45
OE
  Top 0.406: R9.1 20.63,44.28 22.22,42.7 22.22,35.39 22.86,34.76 BU1A.6
  Bottom 0.406: BU1A.6 ST1.10
PAGEL  (via drill 0.7)
  Top 0.406: v23.17,44.92 v23.17,53.17
  Bottom 0.406: ST1.18 BU1A.2 v23.17,44.92 | v23.17,53.17 R6.1
PE  (via drill 0.7)
  Top 0.406: X1.12 15.87,16.52 v15.87,15.71
  Bottom 0.406: v15.87,15.71 16.19,16.03 21.9,16.03 23.81,17.93 26.98,17.93 27.93,16.98 JP2.2
R/B  (via drill 0.7)
  Top 0.406: v29.06,42.38 29.06,22.38 27.79,21.11 R16.1
  Bottom 0.406: ST1.16 v29.06,42.38 BU1A.3
RESET  (via drill 0.7)
  Top 0.406: T1.C 60.32,76.35 54.92,70.95 52.07,70.95 49.53,68.41 49.53,61.75 v47.3,59.52 | BU1A.1 25.39,50 28.57,53.17 28.57,58.89 29.2,59.52 v29.84,59.52
  Bottom 0.406: BU1A.1 ST1.20 | T1.C 60.32,78.26 61.27,79.21 66.03,79.21 67.3,77.94 R3.1 R4.1 | v29.84,59.52 v47.3,59.52
RESET-ISP  (via drill 0.7)
  Top 0.406: IC1.3 27.93,11.27 29.2,10 v29.2,2.69 | ST2.5 84.77,4.28 85.72,5.23 85.72,13.81 85.05,14.47 83.18,14.47 BU2.5 | BU2.5
  Bottom 0.406: v29.2,2.69 29.2,2.06 29.84,1.42 82.23,1.42 83.18,2.38 ST2.5 | 67.22,17.97 S2.4 | 67.22,17.97 S2.3 73.66,17.97 73.63,17.94 73.69,17.88 74.61,17.88 76.78,15.71 82.19,15.71 83.18,14.72 BU2.5 | 67.22,17.97 | BU2.5
SCK
  Top 0.406: IC1.8 17.77,2.69 19.04,1.42 63.81,1.42 64.77,2.38 78.73,2.38 ST2.3 81.91,5.55 81.91,13.49 80.97,14.43 80.63,14.43 | 80.63,14.43 80.6,14.43 | 80.63,14.43 BU2.3
VCC-ISP
  Top 0.406: ST2.2 76.19,8.73 76.19,16.03 77.15,16.98 BU2.2 | JP1.3 30.16,52.22 32.06,50.32 33.97,50.32 35.24,49.05 35.24,22.7 38.1,19.84 38.1,9.36 38.1,9.35 R28.1 | BU2.2
  Bottom 0.406: IC1.14 35.55,4.92 36.83,6.19 R28.1 36.79,8.06 36.79,8.04 69.58,8.04 C9.2 76.83,7.77 77.78,6.82 ST2.2 78.1,6.86 79.39,8.15 89.02,8.15 R27.1 | R27.1
VCC-PROG  (via drill 0.7)
  Top 0.406: T3.C 60.32,65.24 57.78,62.7 v57.78,55.08 | v40,55.08 BU1B.1 40.95,47.46 42.22,46.19 42.22,25.23 42.86,24.6 RN1.1
  Bottom 0.406: BU1B.1 ST1.19 | T3.C 60.32,66.51 61.91,68.1 66.67,68.1 67.94,66.83 C6.1 R5.1 | v40,55.08 v57.78,55.08
WR  (via drill 0.7)
  Top 0.406: v21.9,32.22 21.27,32.85 21.27,40.16 20.31,41.11 R10.1
  Bottom 0.406: ST1.8 BU1A.7 v21.9,32.22
XA0  (via drill 0.7)
  Top 0.406: v17.77,29.04 v17.77,35.08 | IC2.11 41.27,8.41 40,9.68 40,20.47 36.51,23.96 v36.51,28.41
  Bottom 0.406: v17.77,35.08 R12.1 | v17.77,29.04 19.88,29.04 21.79,27.14 BU1A.9 ST1.4 32.7,28.41 v36.51,28.41
XA1  (via drill 0.7)
  Top 0.406: v32.7,33.49 32.7,25.55 33.65,24.6 ST1.1
  Bottom 0.406: ST1.1 BU1B.10 | R13.1 19.68,33.49 v32.7,33.49
XTAL1  (via drill 0.7)
  Top 0.406: BU1A.5 24.44,37.3 23.17,38.57 23.17,43.02 21.27,44.92 v21.27,46.82
  Bottom 0.406: BU1A.5 ST1.12 | v21.27,46.82 R8.1

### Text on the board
Top: 0606 | ISP-HV | Brenner
Bottom: www.b-redemann.de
